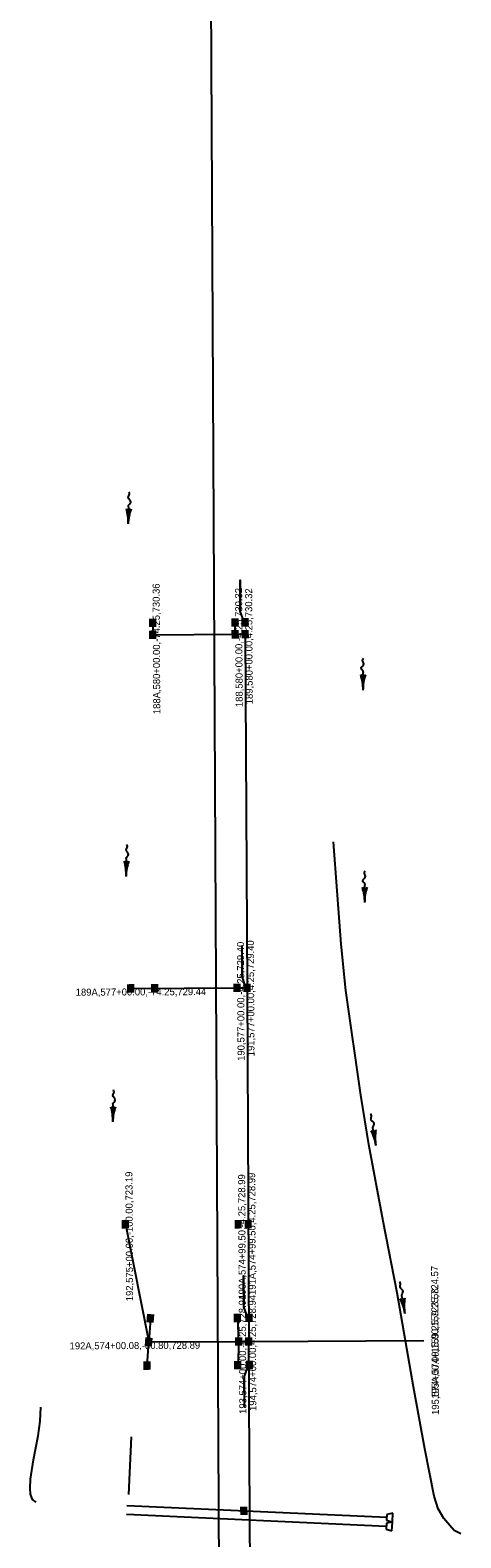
# Model space of a CAD drawing. Extents: x 593481 to 595859, y 101157 to 225994.
# Drawn here: x 594163 to 594529, y 156509 to 157788 of the extents above; entities that cross this region are included whole.
import ezdxf

# ---------------------------------------------------------------- set-up
doc = ezdxf.new("R2010")
doc.units = 0
for name, color, linetype in [('Default', 7, 'Continuous'), ('E_DTM_SpotElev', 7, 'Continuous'), ('E_PROF_GridMin', 7, 'Continuous'), ('Level 6', 7, 'Continuous'), ('P_DRN_SS_UG', 7, 'Continuous'), ('P_MAP_ContoursInter', 7, 'Continuous')]:
    doc.layers.add(name, color=color, linetype=linetype)

msp = doc.modelspace()

# ---------------------------------------------------------------- linework, layer by layer
at = {"layer": 'Default'}
msp.add_line((594334.5, 154382.7), (594308.8, 159385.6), dxfattribs=at)
at = {"layer": 'E_DTM_SpotElev'}
for p, q in [((594246.4, 157368.8), (594246.9, 157382.9)), ((594445.9, 157227.8), (594445.9, 157241.9)), ((594244.6, 157069.8), (594245.1, 157084)), ((594447.3, 157047.5), (594447.3, 157061.7)), ((594233.3, 156861.6), (594233.8, 156875.7)), ((594456.7, 156841.6), (594454.5, 156855.6)), ((594481.4, 156699), (594479.2, 156713))]:
    msp.add_line(p, q, dxfattribs=at)
for points in [[(594244.8, 157381.6), (594246.7, 157378.4), (594248.8, 157381.5)], [(594447.9, 157240.6), (594445.9, 157237.4), (594443.9, 157240.6)], [(594243.1, 157082.7), (594244.9, 157079.4), (594247, 157082.6)], [(594449.3, 157060.3), (594447.3, 157057.1), (594445.3, 157060.3)], [(594231.8, 156874.4), (594233.6, 156871.2), (594235.7, 156874.3)], [(594452.8, 156854), (594455.3, 156851.1), (594456.7, 156854.6)], [(594477.4, 156711.4), (594479.9, 156708.5), (594481.3, 156712)]]:
    msp.add_lwpolyline(points, dxfattribs=at)
for centre, start, end in [((594204.5, 157370.1), 358.1339, 15.8962), ((594288.4, 157367.4), 160.3716, 178.1339), ((594403.9, 157227.8), 0, 17.7623), ((594487.8, 157227.8), 162.2377, 180), ((594202.7, 157071.2), 358.1339, 15.8962), ((594286.6, 157068.5), 160.3716, 178.1339), ((594405.3, 157047.5), 0, 17.7623), ((594489.2, 157047.5), 162.2377, 180), ((594191.4, 156862.9), 358.1339, 15.8962), ((594275.3, 156860.2), 160.3716, 178.1339), ((594415.3, 156835.1), 8.9453, 26.7077), ((594498.2, 156848.2), 171.183, 188.9453), ((594439.9, 156692.5), 8.9453, 26.7077), ((594522.8, 156705.6), 171.183, 188.9453)]:
    msp.add_arc(centre, 42, start, end, dxfattribs=at)
for points in [[(594246.9, 157382.9), (594246.6, 157383.7), (594248.6, 157387.2), (594246.5, 157391.2), (594247.6, 157394), (594247, 157395.8)], [(594445.9, 157241.9), (594446.2, 157242.7), (594444.3, 157246.3), (594446.5, 157250.2), (594445.5, 157253), (594446.2, 157254.8)], [(594245.1, 157084), (594244.8, 157084.8), (594246.8, 157088.3), (594244.7, 157092.3), (594245.8, 157095.1), (594245.2, 157096.8)], [(594447.3, 157061.7), (594447.6, 157062.4), (594445.7, 157066.1), (594447.9, 157070), (594447, 157072.8), (594447.6, 157074.5)], [(594233.8, 156875.7), (594233.5, 156876.5), (594235.5, 156880), (594233.4, 156884), (594234.5, 156886.8), (594233.9, 156888.6)], [(594454.5, 156855.6), (594454.1, 156856.3), (594455.4, 156860.2), (594452.6, 156863.7), (594453.1, 156866.6), (594452.2, 156868.3)], [(594479.2, 156713), (594478.7, 156713.7), (594480, 156717.6), (594477.3, 156721.1), (594477.7, 156724.1), (594476.9, 156725.7)]]:
    msp.add_spline(points, degree=3, dxfattribs=at)
at = {"layer": 'E_PROF_GridMin'}
for p, q in [((594267.4, 157284.8), (594267.4, 157274.8)), ((594267.4, 157274.8), (594337.4, 157275.2)), ((594337.4, 157275.2), (594337.4, 157285.2)), ((594337.4, 157275.2), (594345.9, 157275.2)), ((594345.9, 157275.2), (594347.4, 156975.2)), ((594248.7, 156974.7), (594338.9, 156975.2)), ((594338.9, 156975.2), (594347.4, 156975.2)), ((594347.4, 156975.2), (594349, 156675.2)), ((594244.2, 156774.7), (594263.9, 156674.9)), ((594265.4, 156694.8), (594263.9, 156674.9)), ((594340.5, 156675.2), (594339.4, 156695.2)), ((594262.6, 156654.8), (594263.9, 156674.9)), ((594263.9, 156674.9), (594340.5, 156675.2)), ((594340.5, 156675.2), (594339.6, 156655.2)), ((594340.5, 156675.2), (594350, 156675.2)), ((594350.5, 156375.2), (594349, 156675.2)), ((594350, 156675.2), (594497.4, 156676))]:
    msp.add_line(p, q, dxfattribs=at)
for points in [[(594344.5, 157286.2), (594341.6, 157294.7), (594341.5, 157296.7)], [(594528.9, 156512.1), (594523.2, 156514.8), (594519.5, 156519.1), (594514.4, 156525.1), (594509.6, 156533.2), (594506.1, 156544.1), (594498.4, 156584.3), (594488.6, 156636.9), (594474.7, 156716.6), (594462.8, 156777.4), (594450.9, 156842.3), (594444.1, 156884.2), (594431.2, 156972.9), (594427.4, 157012.2), (594420.9, 157099.1)], [(594346.1, 156976.2), (594343.1, 156984.7), (594343.1, 156986.7)], [(594347.7, 156696.2), (594344.6, 156704.7), (594344.6, 156706.7)], [(594348.1, 156654.2), (594344.9, 156645.8), (594344.9, 156643.8)], [(594168.2, 156538.8), (594165.2, 156541.2), (594163.6, 156545.8), (594163.2, 156550.8), (594163.5, 156558.4), (594165.9, 156574.7), (594170, 156595.1), (594171.6, 156607.7), (594172.2, 156619.6)], [(594247, 156545.3), (594249.2, 156594.3)]]:
    msp.add_lwpolyline(points, dxfattribs=at)
at = {"layer": 'P_DRN_SS_UG'}
for p, q in [((594265.1, 157281.4), (594265.1, 157288.2)), ((594266, 157281.4), (594266, 157288.2)), ((594266.9, 157281.4), (594266.9, 157288.3)), ((594267.8, 157281.4), (594267.8, 157288.3)), ((594268.7, 157281.4), (594268.7, 157288.3)), ((594269.6, 157281.4), (594269.6, 157288.3)), ((594335.1, 157281.7), (594335.1, 157288.6)), ((594336, 157281.7), (594336, 157288.6)), ((594336.9, 157281.7), (594336.9, 157288.6)), ((594337.8, 157281.7), (594337.8, 157288.6)), ((594338.7, 157281.7), (594338.7, 157288.6)), ((594339.6, 157281.7), (594339.6, 157288.6)), ((594343.6, 157281.8), (594343.6, 157288.7)), ((594344.5, 157281.8), (594344.5, 157288.7)), ((594345.4, 157281.8), (594345.4, 157288.7)), ((594346.3, 157281.8), (594346.3, 157288.7)), ((594347.2, 157281.8), (594347.2, 157288.7)), ((594348.1, 157281.8), (594348.1, 157288.7)), ((594265.2, 157271.4), (594265.1, 157278.2)), ((594266.1, 157271.4), (594266, 157278.2)), ((594267, 157271.4), (594266.9, 157278.3)), ((594267.9, 157271.4), (594267.8, 157278.3)), ((594268.8, 157271.4), (594268.7, 157278.3)), ((594269.7, 157271.4), (594269.6, 157278.3)), ((594335.2, 157271.7), (594335.1, 157278.6)), ((594336.1, 157271.7), (594336, 157278.6)), ((594337, 157271.7), (594336.9, 157278.6)), ((594337.9, 157271.7), (594337.8, 157278.6)), ((594338.8, 157271.7), (594338.7, 157278.6)), ((594339.7, 157271.7), (594339.6, 157278.6)), ((594343.7, 157271.8), (594343.6, 157278.6)), ((594344.6, 157271.8), (594344.5, 157278.6)), ((594345.5, 157271.8), (594345.4, 157278.7)), ((594346.4, 157271.8), (594346.3, 157278.7)), ((594347.3, 157271.8), (594347.2, 157278.7)), ((594348.2, 157271.8), (594348.1, 157278.7)), ((594246.4, 156971.3), (594246.4, 156978.1)), ((594247.3, 156971.3), (594247.3, 156978.1)), ((594248.2, 156971.3), (594248.2, 156978.2)), ((594249.1, 156971.3), (594249.1, 156978.2)), ((594250, 156971.3), (594250, 156978.2)), ((594250.9, 156971.3), (594250.9, 156978.2)), ((594266.7, 156971.4), (594266.7, 156978.2)), ((594267.6, 156971.4), (594267.6, 156978.2)), ((594268.5, 156971.4), (594268.5, 156978.3)), ((594269.4, 156971.4), (594269.4, 156978.3)), ((594270.3, 156971.4), (594270.3, 156978.3)), ((594271.2, 156971.4), (594271.2, 156978.3)), ((594336.7, 156971.7), (594336.7, 156978.6)), ((594337.6, 156971.7), (594337.6, 156978.6)), ((594338.5, 156971.7), (594338.5, 156978.6)), ((594339.4, 156971.7), (594339.4, 156978.6)), ((594340.3, 156971.7), (594340.3, 156978.6)), ((594341.2, 156971.8), (594341.2, 156978.6)), ((594345.2, 156971.8), (594345.2, 156978.6)), ((594346.1, 156971.8), (594346.1, 156978.7)), ((594347, 156971.8), (594347, 156978.7)), ((594347.9, 156971.8), (594347.9, 156978.7)), ((594348.8, 156971.8), (594348.8, 156978.7)), ((594349.7, 156971.8), (594349.7, 156978.7)), ((594242, 156771.2), (594242, 156778.1)), ((594242.9, 156771.2), (594242.9, 156778.1)), ((594243.8, 156771.3), (594243.8, 156778.1)), ((594244.7, 156771.3), (594244.7, 156778.1)), ((594245.6, 156771.3), (594245.6, 156778.1)), ((594246.5, 156771.3), (594246.5, 156778.1)), ((594337.7, 156771.2), (594337.7, 156778.1)), ((594338.6, 156771.2), (594338.6, 156778.1)), ((594339.5, 156771.2), (594339.5, 156778.1)), ((594340.4, 156771.2), (594340.4, 156778.1)), ((594341.3, 156771.3), (594341.3, 156778.1)), ((594342.2, 156771.3), (594342.2, 156778.1)), ((594346.2, 156771.3), (594346.2, 156778.2)), ((594347.1, 156771.3), (594347.1, 156778.2)), ((594348, 156771.3), (594348, 156778.2)), ((594348.9, 156771.3), (594348.9, 156778.2)), ((594349.8, 156771.3), (594349.8, 156778.2)), ((594350.7, 156771.3), (594350.7, 156778.2)), ((594262.9, 156691.6), (594263.4, 156698.4)), ((594263.8, 156691.5), (594264.3, 156698.3)), ((594264.7, 156691.4), (594265.2, 156698.3)), ((594265.6, 156691.3), (594266.1, 156698.2)), ((594266.5, 156691.3), (594267, 156698.1)), ((594267.4, 156691.2), (594267.9, 156698.1)), ((594337.1, 156691.7), (594337.1, 156698.6)), ((594338, 156691.7), (594338, 156698.6)), ((594338.9, 156691.7), (594338.9, 156698.6)), ((594339.8, 156691.7), (594339.8, 156698.6)), ((594340.7, 156691.7), (594340.7, 156698.6)), ((594341.6, 156691.8), (594341.6, 156698.6)), ((594346.8, 156691.8), (594346.8, 156698.7)), ((594347.7, 156691.8), (594347.7, 156698.7)), ((594348.6, 156691.8), (594348.6, 156698.7)), ((594349.5, 156691.8), (594349.5, 156698.7)), ((594350.4, 156691.8), (594350.4, 156698.7)), ((594351.3, 156691.8), (594351.3, 156698.7)), ((594261.4, 156671.6), (594261.9, 156678.5)), ((594262.3, 156671.5), (594262.8, 156678.4)), ((594263.2, 156671.5), (594263.7, 156678.3)), ((594264.1, 156671.4), (594264.6, 156678.3)), ((594265, 156671.3), (594265.5, 156678.2)), ((594265.9, 156671.3), (594266.4, 156678.1)), ((594338.2, 156671.7), (594338.2, 156678.6)), ((594339.1, 156671.7), (594339.1, 156678.6)), ((594340, 156671.7), (594340, 156678.6)), ((594340.9, 156671.7), (594340.9, 156678.6)), ((594341.8, 156671.8), (594341.8, 156678.6)), ((594342.7, 156671.8), (594342.7, 156678.6)), ((594346.7, 156671.8), (594346.7, 156678.7)), ((594347.6, 156671.8), (594347.6, 156678.7)), ((594348.5, 156671.8), (594348.5, 156678.7)), ((594349.4, 156671.8), (594349.4, 156678.7)), ((594350.3, 156671.8), (594350.3, 156678.7)), ((594351.2, 156671.8), (594351.2, 156678.7)), ((594260.4, 156651.3), (594260.3, 156658.2)), ((594261.3, 156651.3), (594261.2, 156658.2)), ((594262.2, 156651.3), (594262.1, 156658.2)), ((594263.1, 156651.3), (594263, 156658.2)), ((594264, 156651.4), (594263.9, 156658.2)), ((594264.9, 156651.4), (594264.8, 156658.2)), ((594337.4, 156651.7), (594337.3, 156658.6)), ((594338.3, 156651.7), (594338.2, 156658.6)), ((594339.2, 156651.7), (594339.1, 156658.6)), ((594340.1, 156651.7), (594340, 156658.6)), ((594341, 156651.7), (594340.9, 156658.6)), ((594341.9, 156651.8), (594341.8, 156658.6)), ((594347.2, 156651.8), (594347.1, 156658.7)), ((594348.1, 156651.8), (594348, 156658.7)), ((594349, 156651.8), (594348.9, 156658.7)), ((594349.9, 156651.8), (594349.8, 156658.7)), ((594350.8, 156651.8), (594350.7, 156658.7)), ((594351.7, 156651.8), (594351.6, 156658.7)), ((594342.6, 156528.2), (594342.5, 156535.1)), ((594343.5, 156528.2), (594343.4, 156535.1)), ((594344.4, 156528.2), (594344.3, 156535.1)), ((594345.3, 156528.2), (594345.2, 156535.1)), ((594346.2, 156528.2), (594346.1, 156535.1)), ((594347.1, 156528.2), (594347, 156535.1))]:
    msp.add_line(p, q, dxfattribs=at)
for points in [[(594341.3, 157296.7), (594341.8, 157296.7), (594341.7, 157320.7), (594341.2, 157320.7)], [(594268.4, 157283.8), (594268.3, 157285.8), (594266.3, 157285.8), (594266.4, 157283.8)], [(594338.4, 157284.2), (594338.3, 157286.2), (594336.3, 157286.2), (594336.4, 157284.2)], [(594346.9, 157284.2), (594346.9, 157286.2), (594344.9, 157286.2), (594344.9, 157284.2)], [(594268.4, 157273.8), (594268.4, 157275.8), (594266.4, 157275.8), (594266.4, 157273.8)], [(594338.4, 157274.2), (594338.4, 157276.2), (594336.4, 157276.2), (594336.4, 157274.2)], [(594346.9, 157274.2), (594346.9, 157276.2), (594344.9, 157276.2), (594344.9, 157274.2)], [(594342.9, 156986.7), (594343.4, 156986.7), (594343.2, 157010.7), (594342.8, 157010.7)], [(594249.7, 156973.7), (594249.7, 156975.7), (594247.7, 156975.7), (594247.7, 156973.7)], [(594269.9, 156973.8), (594269.9, 156975.8), (594267.9, 156975.8), (594267.9, 156973.8)], [(594339.9, 156974.2), (594339.9, 156976.2), (594337.9, 156976.2), (594337.9, 156974.2)], [(594348.4, 156974.2), (594348.4, 156976.2), (594346.4, 156976.2), (594346.4, 156974.2)], [(594245.2, 156773.7), (594245.2, 156775.7), (594243.2, 156775.7), (594243.2, 156773.7)], [(594341, 156773.7), (594341, 156775.7), (594339, 156775.7), (594339, 156773.7)], [(594349.5, 156773.7), (594349.5, 156775.7), (594347.5, 156775.7), (594347.5, 156773.7)], [(594344.3, 156706.7), (594344.8, 156706.7), (594344.7, 156730.7), (594344.2, 156730.7)], [(594266.3, 156693.7), (594266.5, 156695.7), (594264.5, 156695.9), (594264.3, 156693.9)], [(594340.4, 156694.2), (594340.4, 156696.2), (594338.4, 156696.2), (594338.4, 156694.2)], [(594350.1, 156694.2), (594350, 156696.2), (594348, 156696.2), (594348.1, 156694.2)], [(594264.9, 156673.8), (594265, 156675.8), (594263, 156675.9), (594262.9, 156673.9)], [(594341.5, 156674.2), (594341.5, 156676.2), (594339.5, 156676.2), (594339.5, 156674.2)], [(594350, 156674.2), (594350, 156676.2), (594348, 156676.2), (594348, 156674.2)], [(594263.6, 156653.8), (594263.6, 156655.8), (594261.6, 156655.8), (594261.6, 156653.8)], [(594340.6, 156654.2), (594340.6, 156656.2), (594338.6, 156656.2), (594338.6, 156654.2)], [(594350.4, 156654.2), (594350.4, 156656.2), (594348.4, 156656.2), (594348.4, 156654.2)], [(594344.8, 156619.8), (594345.3, 156619.8), (594345.1, 156643.8), (594344.7, 156643.8)], [(594345.8, 156530.6), (594345.8, 156532.6), (594343.8, 156532.6), (594343.8, 156530.6)]]:
    msp.add_lwpolyline(points, close=True, dxfattribs=at)
at = {"layer": 'P_MAP_ContoursInter'}
for p, q in [((594245.4, 156536.2), (594466, 156526.1)), ((594244.9, 156528.8), (594465.6, 156518.6)), ((594465.7, 156521.1), (594465.5, 156516.1)), ((594470.8, 156522.1), (594465.7, 156521.1)), ((594466.1, 156528.6), (594465.8, 156523.6)), ((594465.8, 156523.6), (594470.8, 156522.1)), ((594471.1, 156529.6), (594466.1, 156528.6)), ((594470.4, 156514.7), (594470.8, 156522.1)), ((594470.8, 156522.1), (594471.1, 156529.6)), ((594465.5, 156516.1), (594470.4, 156514.7))]:
    msp.add_line(p, q, dxfattribs=at)

# ---------------------------------------------------------------- texts
at = {"layer": 'Level 6'}
for s, rotation, p in [('188A,580+00.00,-74.25,730.36', 90.2941, (594273.7, 157207.4)), ('188,580+00.00,-4.25,730.32', 90.2941, (594343.7, 157213.4)), ('189,580+00.00,4.25,730.32', 90.2941, (594352.2, 157215.8)), ('190,577+00.00,-4.25,729.40', 90.2941, (594345.3, 156913.3)), ('191,577+00.00,4.25,729.40', 90.2941, (594353.7, 156917.2)), ('189A,577+00.00,-74.25,729.44', 0.2941, (594201.9, 156968.5)), ('192,575+00.00,-100.00,723.19', 90.2941, (594250.6, 156709.4)), ('190A,574+99.50,-4.25,728.99', 90.2941, (594346.3, 156710.7)), ('191A,574+99.50,4.25,728.99', 90.2941, (594354.8, 156714.7)), ('195A,574+15.00,159.25,724.57', 90.2941, (594510.2, 156626.7)), ('193,574+00.00,-4.25,728.94', 90.2941, (594346.8, 156613.8)), ('194,574+00.00,4.25,728.94', 90.2941, (594355.3, 156616.3)), ('195,574+00.00,159.25,723.58', 90.2941, (594510.3, 156612.9)), ('192A,574+00.08,-80.80,728.89', 0.2941, (594196.7, 156668.5))]:
    msp.add_text(s, height=6, rotation=rotation, dxfattribs=at).set_placement(p)

doc.saveas('drawing.dxf')
